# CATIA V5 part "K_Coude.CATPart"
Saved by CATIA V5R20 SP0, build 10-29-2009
Part number: Coude
Publications: "demilargeur_coude", "epaisseur_coude", "Arête", "rayonpivot_bras24", "rayonpivot_bras21"
Bounding box of the stored display mesh (mm): x 0 to 6, y -5 to 84.99, z -84.99 to 5.015
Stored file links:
  G:\Khaled_CFAO_2011\SIL\SIL_GR2\zthiebault\Khaled\CAD_ThinkMOTION\K_Coude.CATPart
  F:\Projet Thinkmotion\Catia\FINAL\HabillageFinal.CATProduct
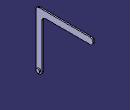
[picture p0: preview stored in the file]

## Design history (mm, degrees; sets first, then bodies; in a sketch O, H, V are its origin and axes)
Parameters
  demilargeur_coude = 5 mm
  epaisseur_coude = 2 mm
  rayonpivot_bras24 = 3 mm {= demilargeur_coude -2mm}
  rayonpivot_bras21 = 3 mm {= demilargeur_coude -2mm}
External parameters (linked from other documents)
  `External.épaisseur_bras24` = 2 mm
  External.epaisseur_bras21 = 2 mm
Set1
  Point1 "Point_base_coude_haut": stored without definition
Set2
  Point2 "Point_base_coude_bas": linked copy from another document
  Point3 "Point_base_coude_haut": linked copy from another document
  DatumPoint1 "point_base_coude_milieu": linked copy from another document
  Plane1 "Plan zx_coude": linked copy from another document
Body1 (main body)
  Sketch1 on yz-plane, origin (0, 0, 0), H (0, 1, 0), V (0, 0, 1)
    line L1 (5.0009, -4.9991) -> (5.0145, -79.9991)
    arc A1 centre (0.0145, -80) radius 5 from (5.0145, -79.9991) to (-4.9855, -80.0009) cw
    point P3 (0.0145, -80)
    line L2 (-4.9855, -80.0009) -> (-5.0009, 4.9991)
    line L3 (-5.0009, 4.9991) -> (79.9991, 5.0145)
    arc A2 centre (80, 0.0145) radius 5 from (79.9991, 5.0145) to (80.0009, -4.9855) cw
    point P7 (80, 0.0145)
    line L4 (80.0009, -4.9855) -> (5.0009, -4.9991)
    reference projected point E1 (80, 0.0145) from Point3
    reference projected point E2 (0.0145, -80) from Point2
    reference intersected line E3 through (0, 0) direction (1, 0.0002) from Plane1
    radius A1 = 5
    radius A2 = 5
    tangency: L3 A2, L4 A2, A1 L1, A1 L2
    coincidence: E1 P7, E2 P3
    parallelism: L4 L3, L2 L1, E3 L3
    perpendicularity: L2 L3
  Pad1: profile Sketch1, direction (1, 0, 0), length 4 {= `External.épaisseur_bras24` +epaisseur_coude}, opposite side length -2 {= -`External.épaisseur_bras24`}
  Fillet1: radius 5, on edge [face of Pad1 from Sketch1.L4 | face of Pad1 from Sketch1.L1]; edge [face of Pad1 from Sketch1.L2 | face of Pad1 from Sketch1.L3]
  Sketch2 on end face of Pad1, origin (4, 0, 0), H (0, 1, 0), V (0, 0, 1)
    circle A1 centre (80, 0.0145) radius 3
    reference projected arc E1 centre (80, 0.0145) radius 5 from (80.0009, -4.9855) to (79.9991, 5.0145) ccw from edge [face of Pad1 from Sketch1.A2 | end face of Pad1]
    radius A1 = 3 {= rayonpivot_bras24}
    concentricity: E1 A1
  Pad2: profile Sketch2, direction (-1, 0, 0), length 4 {= epaisseur_coude +`External.épaisseur_bras24`}
  Sketch3 on start face of Pad1, origin (2, 0, 0), H (0, -1, 0), V (0, 0, 1)
    circle A1 centre (-0.0145, -80) radius 3
    reference projected arc E1 centre (-0.0145, -80) radius 5 from (-5.0145, -79.9991) to (4.9855, -80.0009) ccw from edge [start face of Pad1 | face of Pad1 from Sketch1.A1]
    radius A1 = 3 {= rayonpivot_bras21}
    concentricity: A1 E1
  Pad3: profile Sketch3, direction (1, 0, 0), length 4 {= epaisseur_coude +External.epaisseur_bras21}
